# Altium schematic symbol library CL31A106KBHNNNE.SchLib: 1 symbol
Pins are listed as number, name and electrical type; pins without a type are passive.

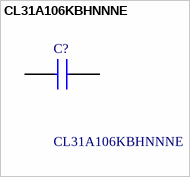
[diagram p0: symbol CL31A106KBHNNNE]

## CL31A106KBHNNNE
designator C?
Samsung Multi-layer Ceramic Capacitor, 1206, 10uF, 50V; Geometry.Height: 1.8mm
footprint CAPC3216X180N
pins: 1, 2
